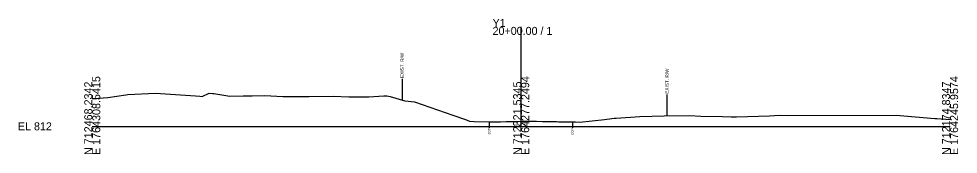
# Model space of a CAD drawing. Extents: x -26 to 1303, y -10 to 9524.
# Drawn here: x 974.3 to 1302.8, y -9.7 to 37.5 of the extents above; entities that cross this region are included whole.
import ezdxf

# ---------------------------------------------------------------- set-up
doc = ezdxf.new("R2010")
doc.units = 0
for name, color, linetype in [('Default', 7, 'Continuous'), ('Exist Cross Section Cell', 7, 'Continuous'), ('Exist XS Center Line Elevation Label', 7, 'Continuous'), ('Exist XS Ground Line', 7, 'Continuous'), ('Old_Level_10', 7, 'Continuous')]:
    doc.layers.add(name, color=color, linetype=linetype)

msp = doc.modelspace()

# ---------------------------------------------------------------- linework, layer by layer
at = {"layer": 'Exist Cross Section Cell'}
for p, q in [((1150, 0), (1150, 34.66)), ((1000, 0), (1150, 0)), ((1150, 0), (1300, 0))]:
    msp.add_line(p, q, dxfattribs=at)
at = {"layer": 'Exist XS Ground Line'}
msp.add_lwpolyline([(1000, 9.72), (1002.22, 9.87), (1005.48, 10.02), (1011.71, 10.95), (1012.39, 11.08), (1022.09, 11.52), (1036.09, 10.59), (1037.64, 10.46), (1038.4, 10.41), (1040.89, 11.55), (1042.03, 11.48), (1042.52, 11.47), (1048.07, 10.56), (1052.75, 10.58), (1055.87, 10.64), (1060.41, 10.73), (1066.68, 10.43), (1070.05, 10.36), (1073.02, 10.39), (1075.89, 10.43), (1084.3, 10.51), (1089.74, 10.27), (1096.71, 10.3), (1101.95, 10.58), (1103.03, 10.58), (1104.18, 10.37), (1109.33, 8.89), (1112.67, 8.55), (1126.11, 3.93), (1130.56, 2.44), (1131.98, 1.77), (1133.51, 1.73), (1138.82, 1.53), (1139.45, 1.55), (1139.85, 1.57), (1140.45, 1.58), (1141.11, 1.6), (1141.66, 1.59), (1142.81, 1.62), (1144.76, 1.67), (1145.18, 1.68), (1145.82, 1.68), (1147.73, 1.69), (1148.98, 1.73), (1150.29, 1.76), (1150.83, 1.77), (1152.39, 1.78), (1152.85, 1.78), (1154.79, 1.76), (1155.4, 1.75), (1157.4, 1.73), (1157.96, 1.71), (1159.51, 1.7), (1160.34, 1.7), (1161.1, 1.67), (1162.05, 1.67), (1162.52, 1.64), (1163.07, 1.62), (1165.32, 1.53), (1165.63, 1.52), (1165.97, 1.53), (1167.92, 1.57), (1169.01, 1.54), (1170.55, 1.47), (1179.16, 2.44), (1181.71, 2.72), (1182.53, 2.83), (1183.23, 2.87), (1191.51, 3.44), (1200.06, 3.65), (1208.93, 3.74), (1212.79, 3.58), (1220.42, 3.46), (1223.48, 3.36), (1225.32, 3.36), (1236.79, 3.69), (1240.31, 3.87), (1243.23, 3.83), (1281.1, 3.94), (1294.69, 2.74), (1295.33, 2.68), (1300, 2.38)], dxfattribs=at)
at = {"layer": 'Old_Level_10'}
for p, q in [((1108.35, 16.57), (1108.35, 9.17)), ((1200.98, 11.06), (1200.98, 3.66)), ((1138.82, 1.53), (1138.82, -0.52)), ((1167.92, 1.57), (1167.92, -0.48))]:
    msp.add_line(p, q, dxfattribs=at)

# ---------------------------------------------------------------- texts
at = {"layer": 'Default'}
msp.add_text('-', height=0.0001, dxfattribs=at).set_placement((1000, 0))
at = {"layer": 'Exist Cross Section Cell'}
for s, p in [('Y1', (1140, 34.66)), ('20+00.00 / 1', (1140, 31.86)), ('EL 812', (974, -1.4))]:
    msp.add_text(s, height=2.8, dxfattribs=at).set_placement(p)
for s, p in [('E 1764308.5415', (1002.8, -10)), ('E 1764277.2494', (1152.8, -10)), ('E 1764245.9574', (1302.8, -10)), ('N 712468.2342', (1000, -10)), ('N 712321.5345', (1150, -10)), ('N 712174.8347', (1300, -10))]:
    msp.add_text(s, height=2.8, rotation=90, dxfattribs=at).set_placement(p)
at = {"layer": 'Exist XS Center Line Elevation Label'}
msp.add_text('813.76', height=1, dxfattribs=at).set_placement((1147.98, -0.24))
at = {"layer": 'Old_Level_10'}
for s, height, p in [('EXIST. R/W', 1.181, (1108.94, 16.87)), ('EXIST. R/W', 1.181, (1201.57, 11.36)), ('EOP', 0.787, (1139.21, -2.92)), ('EOP', 0.787, (1168.31, -2.87))]:
    msp.add_text(s, height=height, rotation=90, dxfattribs=at).set_placement(p)

doc.saveas('drawing.dxf')
